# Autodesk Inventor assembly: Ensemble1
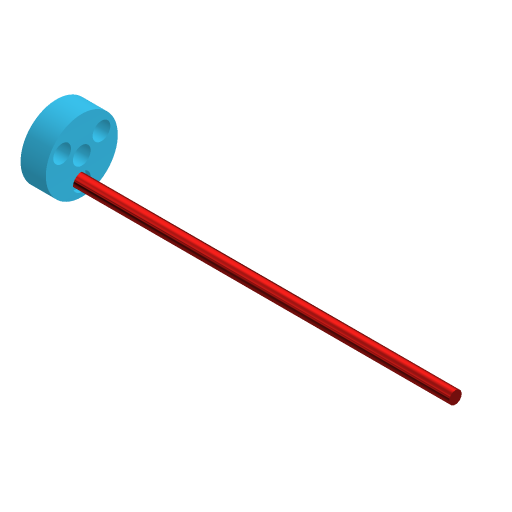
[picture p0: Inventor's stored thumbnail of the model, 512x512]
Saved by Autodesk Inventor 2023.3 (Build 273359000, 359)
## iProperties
Created: 2023-12
Part Number: Ensemble1
Document SubType Name: Assembly
Designer: Thier
Author: Thier
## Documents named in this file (3)
- C:\Travail\BTS TechCom\2-TechnoIndus\21-Meca\214-Systémes Industriels-SI\2141-Pièces Ecrites\21411-Cycle1\214112-TP02Eolienne\2141122-DossierTechniqueEolienne\21411223-Maquette numerique\214112232-CEB-Eolienne\Disque collecteur\Ensemble1.iam
- C:\Travail\BTS TechCom\2-TechnoIndus\21-Meca\214-Systémes Industriels-SI\2141-Pièces Ecrites\21411-Cycle1\214112-TP02Eolienne\2141122-DossierTechniqueEolienne\21411223-Maquette numerique\214112232-CEB-Eolienne\Disque collecteur\Disque collecteur n.ipt
- C:\Travail\BTS TechCom\2-TechnoIndus\21-Meca\214-Systémes Industriels-SI\2141-Pièces Ecrites\21411-Cycle1\214112-TP02Eolienne\2141122-DossierTechniqueEolienne\21411223-Maquette numerique\214112232-CEB-Eolienne\Disque collecteur\phase.ipt
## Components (2 placed, 2 different names)
1. Disque collecteur n:1 — Logement:1
2. phase:1 — Logement:1
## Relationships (1: Insert 1)
- Logement:1 [Insert]: Disque collecteur n:1 ↔ phase:1
